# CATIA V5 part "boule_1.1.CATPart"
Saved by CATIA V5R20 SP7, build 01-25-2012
Part number: boule_1.1
Bounding box of the stored display mesh (mm): x 430.778 to 526.604, y 81.518 to 181.504, z 1056.306 to 1153.959
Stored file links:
  D:\thinkmotion-MPB\Dropbox\MMS_GR3\CFAO_2010_bfoltzer\CFAO_bfoltzer\boule_1.1.CATPart
  D:\ecole\thinkmotion\Eolienne.CATProduct
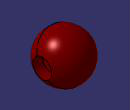
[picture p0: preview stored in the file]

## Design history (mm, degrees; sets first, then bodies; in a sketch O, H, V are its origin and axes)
External parameters (linked from other documents)
  External.rayon_barre = 20 mm
Set1
  Plane1: linked copy from another document
  Point1 to Point3: linked copy from another document
  Line1: linked copy from another document
  Point4: linked copy from another document
  Plane2: linked copy from another document
  Plane3: linked copy from another document
Body1 (main body)
  Sketch1 on Plane1, origin (0, 247.3378, -2.2107), H (-1, 0, 0), V (0, -0.1041, 0.9946)
    arc A1 centre (-480.7782, 1112.2228) radius 50 from (-430.7782, 1112.2228) to (-530.7782, 1112.2228) cw
    point P1 (-480.7782, 1112.2228)
    point P2 (-430.7782, 1112.2228)
    point P3 (-530.7782, 1112.2228)
    reference projected point E1 (-430.7782, 1112.2228) from Point1
    reference projected point E2 (-480.7782, 1112.2228) from Point2
    reference projected point E3 (-530.7782, 1112.2228) from Point3
    coincidence: P2 E1, P1 E2, P3 E3
  Shaft1: profile Sketch1, axis Line1, angle 360
  Sketch2 on {plane type Tangent, Support face of Shaft1 from Sketch1.A1, RefPoint Point4}, origin (480.7782, 1619.9396, 1209.5438), H (1, 0, 0), V (0, 0.9946, 0.1041)
    point P1 (0, -1491.3308)
    reference projected point E1 (0, -1491.3308) from Point4
    coincidence: E1 P1
  Hole1: placed by Sketch2, at (480.7782, 136.7177, 1054.2364) direction (0, -0.1041, 0.9946), diameter 40 {= External.rayon_barre *2}, up to Plane2
  Sketch3 on {plane type Tangent, Support face of Shaft1 from Sketch1.A1, RefPoint Point3}, origin (530.7782, 9.8948, 1099.9555), H (0, 1, 0), V (0, 0, -1)
    point P1 (121.6159, -4.009)
    reference projected point E1 (121.6159, -4.009) from Point3
    coincidence: E1 P1
  Hole2: placed by Sketch3, at (530.7782, 131.5107, 1103.9645) direction (-1, 0, 0), diameter 40 {= External.rayon_barre *2}, up to Plane3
